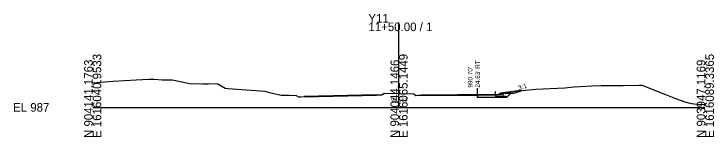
# Model space of a CAD drawing. Extents: x -26 to 203, y -10 to 2019.
# Drawn here: x -25.7 to 202.8, y 1490.3 to 1530.5 of the extents above; entities that cross this region are included whole.
import ezdxf

# ---------------------------------------------------------------- set-up
doc = ezdxf.new("R2010")
doc.units = 0
for name, color, linetype in [('Exist Cross Section Cell', 7, 'Continuous'), ('Exist XS Center Line Elevation Label', 7, 'Continuous'), ('Exist XS Ground Line', 7, 'Continuous'), ('Prop XS Dump Level', 7, 'Continuous'), ('Prop XS Earthwork Shape', 7, 'Continuous'), ('Prop XS EOT Tick Mark', 7, 'Continuous'), ('Prop XS Finish Grade', 7, 'Continuous'), ('Prop XS Finish Grade CurbGutter', 7, 'Continuous'), ('Prop XS Finish Grade Earthwork', 7, 'Continuous'), ('Prop XS Finish Grade Pavement', 7, 'Continuous'), ('Prop XS Hydro Elevations', 7, 'Continuous'), ('Prop XS Pvmt Edge Slope', 7, 'Continuous'), ('Prop XS Side Slope Text', 7, 'Continuous'), ('Prop XS Subgrade CurbGutter', 7, 'Continuous'), ('Prop XS Subgrade Earthwork', 7, 'Continuous')]:
    doc.layers.add(name, color=color, linetype=linetype)

msp = doc.modelspace()

# ---------------------------------------------------------------- linework, layer by layer
at = {"layer": 'Exist Cross Section Cell'}
for p, q in [((100, 1500), (100, 1527.73)), ((0, 1500), (100, 1500)), ((100, 1500), (200, 1500))]:
    msp.add_line(p, q, dxfattribs=at)
at = {"layer": 'Exist XS Ground Line'}
for p, q in [((0, 1508.01), (6.54, 1508.6)), ((6.54, 1508.6), (10.38, 1508.83)), ((10.38, 1508.83), (14.17, 1509.05)), ((14.17, 1509.05), (18.29, 1509.18)), ((18.29, 1509.18), (20.19, 1509.24)), ((20.19, 1509.24), (22.7, 1509.01)), ((22.7, 1509.01), (25.91, 1508.95)), ((25.91, 1508.95), (26.61, 1508.94)), ((26.61, 1508.94), (31.63, 1507.78)), ((31.63, 1507.78), (35.95, 1507.7)), ((35.95, 1507.7), (37.83, 1507.73)), ((37.83, 1507.73), (40.63, 1507.79)), ((40.63, 1507.79), (43.27, 1506.29)), ((43.27, 1506.29), (44.18, 1506.2)), ((44.18, 1506.2), (56.17, 1505.3)), ((144.63, 1505.94), (154.16, 1506.43)), ((154.16, 1506.43), (155.12, 1506.48)), ((155.12, 1506.48), (157.14, 1506.67)), ((157.14, 1506.67), (159.17, 1506.8)), ((159.17, 1506.8), (162.94, 1507.03)), ((162.94, 1507.03), (166.04, 1507.13)), ((166.04, 1507.13), (171.95, 1507.17)), ((171.95, 1507.17), (173.2, 1507.18)), ((173.2, 1507.18), (178.43, 1507.25)), ((178.43, 1507.25), (179.4, 1507.21)), ((179.4, 1507.21), (184.45, 1505.23)), ((56.17, 1505.3), (57.76, 1504.88)), ((57.76, 1504.88), (61.48, 1504.02)), ((61.48, 1504.02), (64.13, 1503.96)), ((64.13, 1503.96), (66.48, 1503.9)), ((66.48, 1503.9), (67.15, 1503.45)), ((77.26, 1503.73), (81.65, 1503.85)), ((81.65, 1503.85), (92.1, 1504.1)), ((92.1, 1504.1), (92.62, 1504.11)), ((92.62, 1504.11), (94.43, 1504.14)), ((94.43, 1504.14), (95.13, 1504.65)), ((95.13, 1504.65), (100, 1504.53)), ((100, 1504.53), (104.82, 1504.4)), ((104.82, 1504.4), (105.52, 1503.93)), ((105.52, 1503.93), (106.27, 1503.96)), ((106.27, 1503.96), (107.27, 1504.01)), ((107.27, 1504.01), (113.55, 1504.06)), ((113.55, 1504.06), (119.2, 1504.13)), ((119.2, 1504.13), (124.66, 1504.12)), ((124.66, 1504.12), (130.58, 1504.14)), ((130.58, 1504.14), (131.53, 1504.14)), ((131.53, 1504.14), (132.4, 1504.14)), ((132.4, 1504.14), (132.72, 1504.38)), ((132.72, 1504.38), (133.1, 1504.67)), ((133.1, 1504.67), (139, 1505.36)), ((139, 1505.36), (144.63, 1505.94)), ((184.45, 1505.23), (187.01, 1504.19)), ((187.01, 1504.19), (190.29, 1502.94)), ((67.15, 1503.45), (67.98, 1503.49)), ((67.98, 1503.49), (69, 1503.54)), ((69, 1503.54), (77.26, 1503.73)), ((190.29, 1502.94), (193.34, 1501.8)), ((193.34, 1501.8), (194.95, 1501.33)), ((194.95, 1501.33), (195.46, 1501.24)), ((195.46, 1501.24), (197.37, 1501.04)), ((197.37, 1501.04), (200, 1500.96))]:
    msp.add_line(p, q, dxfattribs=at)
at = {"layer": 'Prop XS Dump Level'}
msp.add_line((131.5, 1504.15), (124.66, 1504.12), dxfattribs=at)
at = {"layer": 'Prop XS Earthwork Shape'}
for points in [[(135, 1503.6), (135.25, 1503.36), (125.66, 1503.26), (125.66, 1504.13), (130.58, 1504.14), (131.5, 1504.15), (131.5, 1503.57), (134, 1503.59)], [(134, 1503.59), (134, 1504.59), (133.75, 1504.59), (133.62, 1504.55), (133.53, 1504.46), (133.47, 1504.21), (133.37, 1504.12), (133.25, 1504.1), (132.4, 1504.14), (131.78, 1504.14), (131.53, 1504.14), (131.5, 1504.15), (131.5, 1503.57)], [(134, 1504.59), (134.54, 1504.6), (136.54, 1504.64), (137.5, 1504.66), (139.86, 1505.45), (139, 1505.36), (133.1, 1504.67), (132.72, 1504.38), (132.4, 1504.14), (133.25, 1504.1), (133.37, 1504.12), (133.47, 1504.21), (133.53, 1504.46), (133.62, 1504.55), (133.75, 1504.59)], [(134, 1504.59), (134.54, 1504.6), (136.54, 1504.64), (135.25, 1503.36), (135, 1503.6), (134, 1503.59)]]:
    msp.add_lwpolyline(points, close=True, dxfattribs=at)
at = {"layer": 'Prop XS EOT Tick Mark'}
msp.add_line((131.5, 1504.15), (131.5, 1505.15), dxfattribs=at)
at = {"layer": 'Prop XS Finish Grade'}
msp.add_line((134, 1504.59), (136.54, 1504.64), dxfattribs=at)
at = {"layer": 'Prop XS Finish Grade CurbGutter'}
for p, q in [((131.5, 1504.15), (133.25, 1504.1)), ((133.25, 1504.1), (133.37, 1504.12)), ((133.37, 1504.12), (133.47, 1504.21)), ((133.47, 1504.21), (133.53, 1504.46)), ((133.53, 1504.46), (133.62, 1504.55)), ((133.75, 1504.59), (133.62, 1504.55)), ((134, 1504.59), (133.75, 1504.59))]:
    msp.add_line(p, q, dxfattribs=at)
at = {"layer": 'Prop XS Finish Grade Earthwork'}
for p, q in [((134.54, 1504.6), (137.5, 1504.66)), ((137.5, 1504.66), (139.86, 1505.45))]:
    msp.add_line(p, q, dxfattribs=at)
at = {"layer": 'Prop XS Finish Grade Pavement'}
for p, q in [((92.62, 1504.11), (69, 1503.54)), ((92.63, 1503.86), (69.01, 1503.29)), ((92.62, 1504.11), (92.63, 1503.86)), ((119.2, 1504.13), (107.27, 1504.01)), ((107.27, 1504.01), (107.27, 1503.76)), ((119.2, 1503.88), (107.27, 1503.76)), ((124.66, 1504.12), (119.2, 1504.13)), ((125.66, 1503.87), (119.2, 1503.88)), ((131.5, 1504.14), (124.66, 1504.12)), ((69, 1503.54), (69.01, 1503.29))]:
    msp.add_line(p, q, dxfattribs=at)
at = {"layer": 'Prop XS Hydro Elevations'}
msp.add_line((125.66, 1504.13), (125.66, 1506.24), dxfattribs=at)
at = {"layer": 'Prop XS Pvmt Edge Slope'}
for p, q in [((134, 1503.59), (135, 1503.6)), ((135, 1503.6), (135.25, 1503.36))]:
    msp.add_line(p, q, dxfattribs=at)
at = {"layer": 'Prop XS Subgrade CurbGutter'}
for p, q in [((131.5, 1504.15), (131.5, 1503.57)), ((134, 1503.59), (134, 1504.59)), ((131.5, 1503.57), (134, 1503.59))]:
    msp.add_line(p, q, dxfattribs=at)
at = {"layer": 'Prop XS Subgrade Earthwork'}
for p, q in [((125.66, 1504.13), (125.66, 1503.26)), ((135.25, 1503.36), (136.54, 1504.64)), ((125.66, 1503.26), (135.25, 1503.36))]:
    msp.add_line(p, q, dxfattribs=at)

# ---------------------------------------------------------------- texts
at = {"layer": 'Exist Cross Section Cell'}
for s, p in [('Y11', (90, 1527.73)), ('11+50.00 / 1', (90, 1524.93)), ('EL 987', (-26, 1498.6))]:
    msp.add_text(s, height=2.8, dxfattribs=at).set_placement(p)
for s, p in [('N 904141.1763', (0, 1490)), ('E 1616040.9533', (2.8, 1490)), ('N 904044.1466', (100, 1490)), ('E 1616065.1449', (102.8, 1490)), ('N 903947.1169', (200, 1490)), ('E 1616089.3365', (202.8, 1490))]:
    msp.add_text(s, height=2.8, rotation=90, dxfattribs=at).set_placement(p)
at = {"layer": 'Exist XS Center Line Elevation Label'}
msp.add_text('991.53', height=1.25, dxfattribs=at).set_placement((97.45, 1501.9))
at = {"layer": 'Prop XS Hydro Elevations'}
for s, p in [("990.70'", (123.98, 1506.47)), ("24.63' RT", (126.42, 1506.47))]:
    msp.add_text(s, height=1.5, rotation=90, dxfattribs=at).set_placement(p)
at = {"layer": 'Prop XS Side Slope Text'}
msp.add_text('3:1', height=1.5, rotation=18.4349, dxfattribs=at).set_placement((139.21, 1505.55))

doc.saveas('drawing.dxf')
